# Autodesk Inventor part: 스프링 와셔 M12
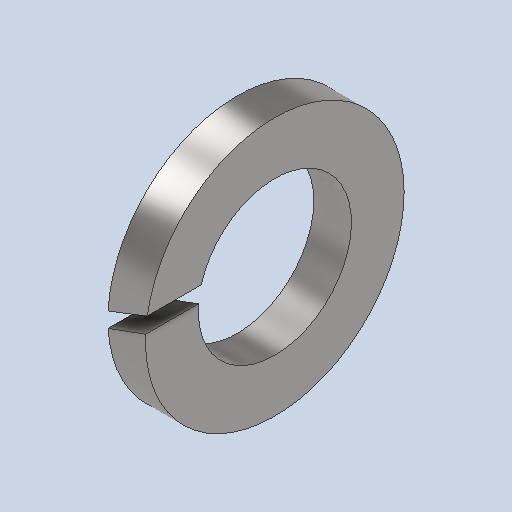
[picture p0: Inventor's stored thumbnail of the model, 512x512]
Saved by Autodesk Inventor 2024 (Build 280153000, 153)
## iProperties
Created: 2024-07
Part Number: 스프링 와셔 M12
Material: 강철, 연강
Description: 스프링 잠금 와셔
Document SubType Name: Modeling
Designer: com
Density: 7.85 g/cm^3
Appearance: 기본값
Author: jhkim
Sending System: Autodesk Inventor 2025
Preprocessor: ST-DEVELOPER v20
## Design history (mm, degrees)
feature "Solid1"
node "솔리드1"
